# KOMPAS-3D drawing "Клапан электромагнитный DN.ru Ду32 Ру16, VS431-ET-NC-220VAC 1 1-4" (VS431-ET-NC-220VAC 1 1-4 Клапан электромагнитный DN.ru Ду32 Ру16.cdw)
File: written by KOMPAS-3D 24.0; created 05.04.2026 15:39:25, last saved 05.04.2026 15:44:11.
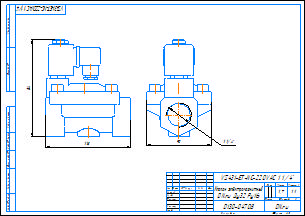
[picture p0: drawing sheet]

Document properties: c3d_UniqueCompID: ef56311e-7521-43dc-8291-0e6108b3d81d; Автор: artio; Класс точности: c; Знак неуказанной шероховатости: Шероховатость не задана; Рассекать на разрезах: Да; c3d_UniqueCompID: ef56311e-7521-43dc-8291-0e6108b3d81d; Автор: artio; Класс точности: c; Знак неуказанной шероховатости: Шероховатость не задана; Рассекать на разрезах: Да; c3d_UniqueCompID: ef56311e-7521-43dc-8291-0e6108b3d81d; Автор: artio; Класс точности: c; Знак неуказанной шероховатости: Шероховатость не задана; Рассекать на разрезах: Да; Автор: artio; Форматы листов документа: A3; Полное имя файла: VS431-ET-NC-220VAC 1 1-4 Клапан электромагнитный DN.ru Ду32 Ру16.m3d; Масса: 1.701; Наименование: Клапан электромагнитный DN.ru Ду32 Ру16; Количество листов документа: 1; Примечание: D130-04708

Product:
- Body: Тело 1  | qty 1
    Масса: 3.709873
- Part/product: Клапан электромагнитный DN.ru Ду32 Ру16  | designation VS431-ET-NC-220VAC 1 1-4
    Масса: 1.701
    Раздел спецификации: Прочие изделия
    Примечание: D130-04708
    additional columns: ef56311e-7521-43dc-8291-0e6108b3d81d; artio; c; Шероховатость не задана; Да

Views: Вид 1, Спереди
Referenced files in C:\Users\artio\OneDrive\Рабочий стол\Клапан электромагнитный DN.ru\VS431\VS431-ET-NC\: VS431-ET-NC-220VAC 3-4 Клапан электромагнитный DN.ru Ду20 Ру16.m3d, VS431-ET-NC-220VAC 1 1-4 Клапан электромагнитный DN.ru Ду32 Ру16.m3d, VS431-ET-NC-220VAC 3-4 Клапан электромагнитный DN.ru Ду20 Ру16.cdw
Referenced files in C:\Users\artio\OneDrive\Рабочий стол\Клапан электромагнитный DN.ru\VS431\VS431-ET-NC\VS431-ET-NC-220VAC\Ду32\: VS431-ET-NC-220VAC 1 1-4 Клапан электромагнитный DN.ru Ду32 Ру16.m3d
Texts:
  VS431-ET-NC-220VAC 1 1-4
  Клапан электромагнитный
  DN.ru Ду32 Ру16
  VS431-ET-NC-220VAC 1 1/4"
  VS431-ET-NC-220VAC 1 1/4"-
  Клапан электромагнитный DN.ru Ду32 Ру16
  VS431-ET-NC-220VAC 1 1-4 Клапан электромагнитный DN.ru Ду32 Ру16
Dimensions and other numbers on the sheet: 0; 3; 2; 4; 90; 1 1/4"; 1:1; 1; 1,7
